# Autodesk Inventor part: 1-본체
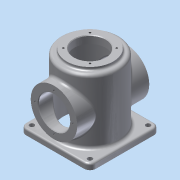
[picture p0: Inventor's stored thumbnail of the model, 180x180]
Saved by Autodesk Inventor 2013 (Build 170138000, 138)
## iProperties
Created: 2015-10
Part Number: 1-본체
Material: 알루미늄 6061
Document SubType Name: Modeling
Designer: Administrator
Mass: 987.678 g
Surface Area: 1044.24 cm^2
Volume: 364.457 cm^3
Density: 2.71 g/cm^3
Author: Administrator
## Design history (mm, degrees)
sketch "스케치1"
  geometry: L1 (-60, 60)-(60, 60); L2 (60, 60)-(60, -60); L3 (60, -60)-(-60, -60); L4 (-60, -60)-(-60, 60); 3 further points
  constraints: 8 end point, 2 midpoint, 2 parallel, 1 horizontal, 1 horizontal alignment, 1 perpendicular, 1 vertical alignment
  dimensions: "d0" = 120 distance of L1.start L1.end; "d2" = 120 distance of L1.end L2.end
extrude "돌출1" new body sketch "스케치1" distance "d3" = 10; taper "d4" = 0 deg
sketch "스케치3"
  geometry: C1 r 50 at (0, 0); 1 further point
  constraints: 1 centre point, 1 coincident
  dimensions: "d5" = 100 diameter of C1
extrude "돌출2" join sketch "스케치3" distance "d7" = 120; taper "d8" = 0 deg
sketch "스케치6"
  geometry: C1 r 50 at (0, 0) reference; C2 r 40 at (0, 0); 1 further point
  constraints: 1 centre point, 1 coincident
  dimensions: "d9" = 80 diameter of C2
extrude "돌출3" join sketch "스케치6" distance "d11" = 5; taper "d12" = 0 deg
node "작업 평면1"
sketch "스케치7"
  geometry: L1 (50, 120)-(-50, 120) reference; L2 (-50, 10)-(50, 10) reference; L3 (60, 0)-(-60, 0) reference; L4 (60, 0)-(60, 10) reference; L5 (-60, 10)-(60, 10) reference; L6 (-60, 0)-(-60, 10) reference; L7 (-50, 10)-(-50, 120) reference; L8 (50, 10)-(50, 120) reference; C1 r 40 at (0, 60); 2 further points
  constraints: 1 centre point, 1 midpoint, 1 vertical alignment
  dimensions: "d14" = 80 diameter of C1; "d16" = 60 distance of point (0, 0) C1.centre
extrude "돌출4" join sketch "스케치7" distance "d17" = 124; taper "d18" = 0 deg
hole "구멍1" diameter "d21" = 54; stored, may be unused: countersink angle "d25" = 90 deg, drill point angle "d27" = 0 deg; dims "d19" = 10, "d20" = 10, "d22" = 6, "d23" = 4, "d24" = 2, "d26" = 8
sketch "스케치8" dims "d28" = 65
  geometry: C1 r 27 at (0, 0) reference; C2 r 40 at (0, 0) reference; 3 further points
  constraints: 2 vertical alignment, 1 coincident, 2 other
hole "구멍2" sketch "스케치8" at (0, -32.5) diameter "d30" = 3.242; stored, may be unused: countersink angle "d34" = 90 deg, drill point angle "d36" = 118 deg; dims "d31" = 8, "d32" = 4, "d33" = 2, "d35" = 10
node "작업 평면2"
node "작업 평면3"
sketch "스케치9"
  geometry: L1 (-3.602, 45.113)-(-3.602, 94.887); L2 (-3.602, 94.887)-(3.602, 94.887); L3 (3.602, 94.887)-(3.602, 45.113); L4 (3.602, 45.113)-(-3.602, 45.113); L5 (40, 125)-(-40, 125) reference; L6 (50, 120)-(-50, 120) reference; L7 (60, 0)-(-60, 0) reference; 5 further points
  constraints: 3 midpoint, 2 vertical alignment, 1 horizontal alignment, 2 other
  dimensions: "d42" = 70 distance from line of point (0, 70) L7
feature "엠보싱1" sketch "스케치9" dims "d0" = 120, "d2" = 120, "d43" = 0.5, "d44" = 0
hole "구멍3" diameter "d47" = 54; stored, may be unused: countersink angle "d51" = 90 deg, drill point angle "d53" = 0 deg; dims "d45" = 10, "d46" = 10, "d48" = 8, "d49" = 4, "d50" = 2, "d52" = 13
sketch "스케치10"
  geometry: C1 r 45 at (0, 0); 1 further point
  constraints: 1 centre point, 1 coincident
  dimensions: "d54" = 90 diameter of C1
extrude "돌출5" cut sketch "스케치10" distance "d56" = 112; taper "d57" = 0 deg
sketch "스케치11"
  geometry: A1 r 32.5 centre (0, 0) between (-22.981, -22.981) and (-22.981, 22.981); 3 further points
  constraints: 4 point on circle, 2 horizontal alignment, 2 vertical alignment, 1 centre point, 1 coincident
  dimensions: "d58" = 65 diameter of A1; "d60" = 90 deg dimension on point (0, 0) A1.end A1.start
hole "구멍4" sketch "스케치11" at (-22.981, -22.981), (-22.981, 22.981), (22.981, 22.981), (22.981, -22.981) diameter "d62" = 3.242; stored, may be unused: countersink angle "d66" = 90 deg, drill point angle "d68" = 118 deg; dims "d63" = 8, "d64" = 4, "d65" = 2, "d67" = 10
sketch "스케치12"
  geometry: 5 further points
  constraints: 2 horizontal alignment, 2 vertical alignment
  dimensions: "d69" = 50 horizontal distance of point (-50, -50) point (0, 0); "d70" = 100 distance of point (50, 50) point (-50, 50); "d71" = 100 distance of point (-50, -50) point (-50, 50); "d72" = 50 horizontal distance of point (-50, 50) point (0, 0)
hole "구멍5" sketch "스케치12" at (-50, -50), (-50, 50), (50, 50), (50, -50) diameter "d73" = 8; stored, may be unused: countersink angle "d77" = 90 deg, drill point angle "d79" = 0 deg; dims "d74" = 8, "d75" = 4, "d76" = 2, "d78" = 10
fillet "모깎기1" dims "d80" = 10
fillet "모깎기2" dims "d81" = 3
chamfer "모따기1" distance "d82" = 1; stored, may be unused: second distance "d83" = 2, angle "d84" = 45 deg
fillet "모깎기3" dims "d85" = 5
fillet "모깎기4" dims "d86" = 5
fillet "모깎기5" dims "d87" = 3
node "솔리드1"
pattern_circular "원형 패턴1" dims angle "d38" = 360 deg
mirror "대칭1"
node "투영된 루프1"
node "투영된 루프2"
node "투영된 루프3"
other parameters: "d13" = 62
